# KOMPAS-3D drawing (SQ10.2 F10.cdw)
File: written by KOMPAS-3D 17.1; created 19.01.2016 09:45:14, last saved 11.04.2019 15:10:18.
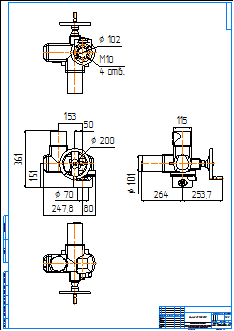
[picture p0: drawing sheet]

Sheet 1: A1, portrait

Title block, sheet 1: name: Привод SQ10.2 F10; material: Внимание! Данный продукт является объектом авторского права ООО «Торговый Дом АДЛ». / Запрещается измрование, распространение / (в том числе путем копирования на другие сайты и ресурсы в Интернете) / или любое иное использование информации и объектов без предварительного / согласия правообладателя (ООО «Торговый Дом АДЛ»).; sheets: 1; organisation: ООО "Торговый дом АДЛ"; sheet format: A1; stored path: C:\Users\kka\KOMPAS_Work\!Trash\Электроприводы\DWG\SQ10.2 F10 220В.cdw

Views: Проекционный вид 2, Проекционный вид 3, Проекционный вид 4
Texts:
  Klimkovich
  ADL
Dimensions and other numbers on the sheet: 200; 151; 80; 247,8; 50; 70; 361; 153; 1 1; 102; 10; 4 отв.; 253,7; 264; 115; 101; 1:2,5; 1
